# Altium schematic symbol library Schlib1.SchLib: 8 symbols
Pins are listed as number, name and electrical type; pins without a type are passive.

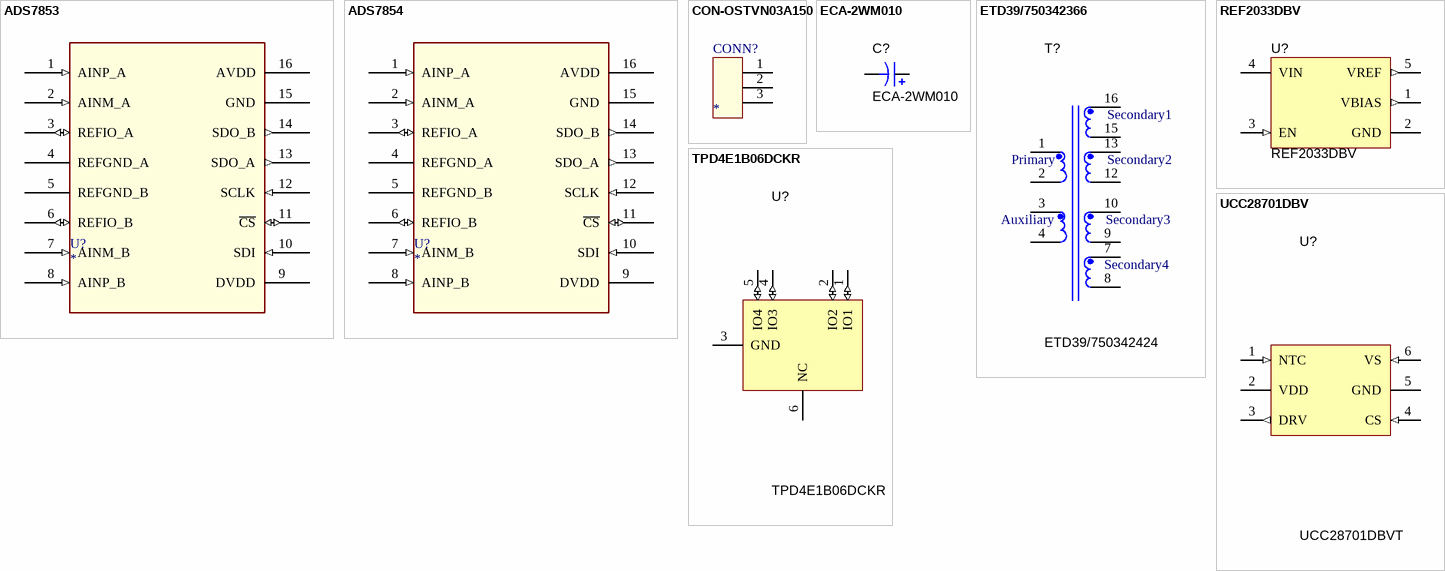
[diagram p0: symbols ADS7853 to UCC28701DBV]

## ADS7853
designator U?
IC ADC 12BIT 1MSPS DUAL 16TSSOP; Manufacturer: Texas Instruments; PartNumber: ADS7853; SymbolCreator: x0213103
footprint PWP24-DIE84X166 (Footprint not found)
pins: 1 AINP_A (in), 2 AINM_A (in), 3 REFIO_A (io), 4 REFGND_A, 5 REFGND_B, 6 REFIO_B (io), 7 AINM_B (in), 8 AINP_B (in), 9 DVDD, 10 SDI (in), 11 ~{CS} (io), 12 SCLK (in), 13 SDO_A (out), 14 SDO_B (out), 15 GND, 16 AVDD

## ADS7854
designator U?
IC ADC 12BIT 1MSPS DUAL 16TSSOP; Manufacturer: Texas Instruments; PartNumber: ADS7854; SymbolCreator: x0213103
footprint PWP24-DIE84X166 (Footprint not found)
pins: 1 AINP_A (in), 2 AINM_A (in), 3 REFIO_A (io), 4 REFGND_A, 5 REFGND_B, 6 REFIO_B (io), 7 AINM_B (in), 8 AINP_B (in), 9 DVDD, 10 SDI (in), 11 ~{CS} (io), 12 SCLK (in), 13 SDO_A (out), 14 SDO_B (out), 15 GND, 16 AVDD

## CON-OSTVN03A150
designator CONN?
CONN TERM BLOCK 2.54MM 3POS PCB; Manufacturer: On Shore Technology Inc; PartNumber: OSTVN03A150; SymbolCreator: x0120606; CompType: Terminal Block
footprint TB_OSTVN03A150_3P
pins: 1, 2, 3

## ECA-2WM010
designator C?
CAP ALUM 1.0UF 450V 20% RADIAL; Manufacturer: Panasonic Electronic Components; Value: 1UF
footprint Radial-CAP_8mmDia _12.5 (Radial, Can)
pins: 1 +, 2 -

## ETD39/750342366
designator T?, comment ETD39/750342424
Transformer,   TH; Manufacturer: wurth elektronik; SymbolCreator: a0411947; U/M: EA
footprint XFORMER_ETD39
pins: 1, 2, 3, 4, 5 hidden, 6 hidden, 7, 8, 9, 10, 11 hidden, 12, 13, 14 hidden, 15, 16

## REF2033DBV
designator U?
DUAL OUTPUT VOLTAGE REFERENCE 3.3V, DBV0005A; Alternate Manufacturer: None; Manufacturer: Texas Instruments; SymbolCreator: a0799628; CompType: IC; U/M: EA
footprint DBV0005A_N
footprint DBV0005A_M
footprint DBV0005A_L
pins: 1 VBIAS (out), 2 GND (power), 3 EN (in), 4 VIN (power), 5 VREF (out)

## TPD4E1B06DCKR
designator U?
TVS DIODE 5.5VWM 14.5VC SC70-6; Manufacturer: TI; U/M: EA
pins: 1 IO1 (io), 2 IO2 (io), 3 GND (power), 4 IO3 (io), 5 IO4 (io), 6 NC

## UCC28701DBV
designator U?, comment UCC28701DBVT
IC, Constant Voltage, Constant Current PWM With Primary Side Regulation; Manufacturer: TI; SymbolCreator: a0411947; CompType: Transformer; Value: UCC2871xDBV; U/M: EA
footprint DBV-6 (Footprint not found)
pins: 1 NTC (in), 2 VDD (power), 3 DRV (out), 4 CS (in), 5 GND (power), 6 VS (in)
